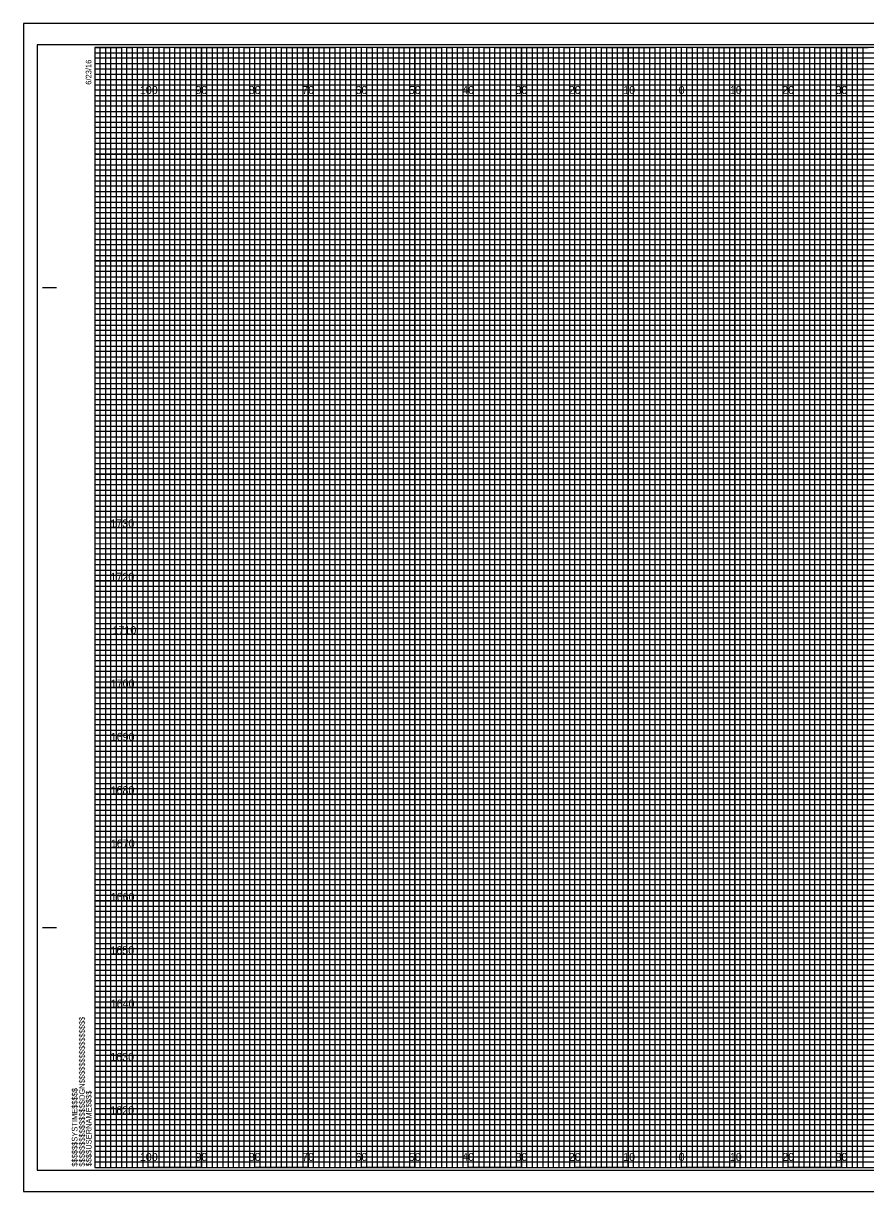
# Model space of a CAD drawing. Extents: x -13 to 323, y -5 to 6154.
# Drawn here: x -13.4 to 144.5, y 2415.5 to 2634.5 of the extents above; entities that cross this region are included whole.
import ezdxf

# ---------------------------------------------------------------- set-up
doc = ezdxf.new("R2010")
doc.units = 0
for name, color, linetype in [('Prop Retaining Wall', 7, 'Continuous'), ('Prop XS Alignment Label', 7, 'Continuous'), ('Prop XS DDE', 7, 'Continuous'), ('Prop XS DDE Elevations', 7, 'Continuous'), ('Prop XS DDE Slope Text', 7, 'Continuous'), ('Prop XS Earthwork Shape', 7, 'Continuous'), ('Prop XS Elevation Labels', 7, 'Continuous'), ('Prop XS Station Labels', 7, 'Continuous'), ('Raster_Level_0', 7, 'Continuous'), ('Scratch_Level_3', 7, 'Continuous'), ('Sheet Cutting Line CELL', 7, 'Continuous')]:
    doc.layers.add(name, color=color, linetype=linetype)

msp = doc.modelspace()

# ---------------------------------------------------------------- linework, layer by layer
at = {"layer": 'Prop Retaining Wall'}
for p, q in [((0, 2629), (260, 2629)), ((260, 2627.98), (0, 2627.98)), ((0, 2627.98), (0, 2627)), ((0, 2627), (260, 2627)), ((260, 2625.89), (0, 2625.89)), ((0, 2625.89), (0, 2624)), ((0, 2624), (320, 2624))]:
    msp.add_line(p, q, dxfattribs=at)
for points in [[(0, 2623), (270, 2623), (320, 2623), (320, 2622), (0, 2622)], [(0, 2621), (320, 2621), (320, 2619), (0, 2619)], [(0, 2618), (320, 2618), (320, 2617), (0, 2616.98)], [(0, 2616), (320, 2616), (320, 2614), (0, 2614)], [(0, 2613), (320, 2613), (320, 2612), (0, 2612)], [(0, 2611), (320, 2611), (320, 2609), (0, 2609)], [(0, 2608), (320, 2608), (320, 2607), (0, 2607)], [(0, 2606), (320, 2606), (320, 2604), (0, 2604)], [(0, 2603), (320, 2603), (320, 2602), (0, 2602)], [(0, 2601), (320, 2601), (320, 2599), (0, 2599)], [(0, 2598), (320, 2598), (320, 2597), (0, 2597)], [(0, 2596), (320, 2596), (320, 2593.95), (320, 2593), (320, 2592), (0, 2592)], [(0, 2594), (320, 2594), (320, 2593), (0, 2593)], [(0, 2591), (320, 2591), (320, 2589), (0, 2589.03)], [(0, 2589.03), (320, 2589), (320, 2588), (0, 2588)], [(0, 2587), (320, 2587), (320, 2586), (0, 2586)], [(0, 2584), (320, 2584), (320, 2583), (0, 2583)], [(0, 2582), (320, 2582), (320, 2581), (0, 2581)], [(-0.07, 2578.89), (320, 2578.89), (320, 2577.88), (-0.07, 2577.88)], [(0, 2577), (320, 2577), (320, 2576), (0, 2576)], [(0, 2574), (320, 2574), (320, 2573), (0, 2573)], [(0, 2572), (320, 2572), (320, 2571), (0, 2571)], [(0, 2569), (320, 2569), (320, 2568), (0, 2568)], [(0, 2567), (320, 2567), (320, 2566), (0, 2566)], [(0, 2564), (320, 2564), (320, 2563), (0, 2563)], [(0, 2562), (320, 2562), (320, 2561), (0, 2561)], [(0, 2559), (320, 2559), (319.99, 2557.98), (0, 2558)], [(0, 2557), (320, 2557), (320, 2556), (0, 2556)], [(0, 2554), (320, 2554), (320, 2553), (0, 2553)], [(0, 2552), (320, 2552), (320, 2551), (0, 2551)], [(0, 2549), (320, 2549), (320, 2548), (0, 2548)], [(0, 2547), (320, 2547), (320, 2546), (0, 2546)], [(0, 2544), (320, 2544), (320, 2543), (0, 2543)], [(0, 2542), (320, 2542), (320, 2541), (0, 2541)], [(0, 2539), (320, 2539), (320, 2538), (0, 2538)], [(0, 2536.99), (320.07, 2536.91), (320, 2536), (0, 2536)], [(0, 2534), (320, 2534), (320, 2533), (0, 2533)], [(0, 2532), (320, 2532), (320, 2531), (0, 2531)], [(0, 2529), (320, 2529), (320, 2528), (0, 2528)], [(0, 2527), (320, 2527), (320, 2526), (0, 2526)], [(0, 2524), (320, 2524), (320, 2523), (0, 2523)], [(0, 2522), (320, 2522), (320, 2521), (0, 2521)], [(0, 2519), (320, 2519), (320, 2518), (0, 2518)], [(0, 2517), (320, 2517), (320, 2516), (0, 2516)], [(0, 2514), (320, 2514), (320, 2513), (0, 2513)], [(0, 2512), (320, 2512), (320, 2511), (0, 2511)], [(0, 2509), (320, 2509), (320, 2508), (0, 2508)], [(0, 2507), (320, 2507), (320, 2506), (0, 2506)], [(0, 2504), (320, 2504), (320, 2503), (0, 2503)], [(0, 2502), (320, 2502), (320, 2501), (0, 2501)], [(0, 2499), (320, 2499), (319.99, 2497.98), (0, 2498)], [(0, 2497), (320, 2497), (320, 2496), (0, 2496)], [(0, 2494), (320, 2494), (320, 2493), (0, 2493)], [(0, 2492), (320, 2492), (320, 2491), (0, 2491)], [(0, 2489), (320, 2489), (320, 2488), (0, 2488)], [(0, 2487), (320, 2487), (320, 2486), (0, 2486)], [(0, 2484), (320, 2484), (320, 2483), (0, 2483)], [(0, 2482), (320, 2482), (320, 2481), (0, 2481)], [(0, 2479), (320, 2479), (320, 2478), (0, 2478)], [(0, 2476.99), (320.07, 2476.91), (320, 2476), (0, 2476)], [(0, 2474), (320, 2474), (320, 2473), (0, 2473)], [(0, 2472), (320, 2472), (320, 2471), (0, 2471)], [(0, 2469), (320, 2469), (320, 2468), (0, 2468)], [(0, 2467), (320, 2467), (320, 2466), (0, 2466)], [(0, 2464), (320, 2464), (320, 2463), (0, 2463)], [(0, 2462), (320, 2462), (320, 2461), (0, 2461)], [(0, 2459), (320, 2459), (320, 2458), (0, 2458)], [(0, 2457), (320, 2457), (320, 2456), (0, 2456)], [(0, 2454), (320, 2454), (320, 2453), (0, 2453)], [(0, 2452), (320, 2452), (320, 2451), (0, 2451)], [(0, 2449), (320, 2449), (320, 2448), (0, 2448)], [(0, 2447), (320, 2447), (320, 2446), (0, 2446)], [(0, 2444), (320, 2444), (320, 2443), (0, 2443)], [(0, 2442), (320, 2442), (320, 2441), (0, 2441)], [(0, 2439), (320, 2439), (320, 2438), (0, 2438)], [(0, 2437), (320, 2437), (320, 2436), (0, 2436)], [(0, 2434), (320, 2434), (320, 2433), (0, 2433)], [(0, 2432), (320, 2432), (320, 2431), (0, 2431)], [(0, 2429), (320, 2429), (320, 2428), (0, 2428)], [(0, 2427), (320, 2427), (320, 2426), (0, 2426)], [(0, 2424), (320, 2424), (320, 2423), (0, 2423)], [(0, 2422), (320, 2422), (320, 2421), (0, 2421)]]:
    msp.add_lwpolyline(points, dxfattribs=at)
at = {"layer": 'Prop XS Alignment Label'}
for p, q in [((-9.8, 2585), (-7.3, 2585)), ((-9.7, 2585), (-7.2, 2585)), ((-9.8, 2465), (-7.3, 2465)), ((-9.7, 2465), (-7.2, 2465)), ((0, 2420), (0, 2420)), ((0, 2420), (0, 2420)), ((0, 2420), (0, 2420)), ((0, 2420), (0, 2420)), ((0, 2420), (0, 2420)), ((0, 2420), (0, 2420)), ((0, 2420), (0, 2420))]:
    msp.add_line(p, q, dxfattribs=at)
msp.add_lwpolyline([(320, 2630), (0, 2630), (0, 2420), (320, 2420)], close=True, dxfattribs=at)
at = {"layer": 'Prop XS DDE'}
msp.add_lwpolyline([(-13.4, 2415.5), (323.3, 2415.5), (323.3, 2634.5), (-13.4, 2634.5)], close=True, dxfattribs=at)
at = {"layer": 'Prop XS DDE Elevations'}
for p, q in [((10, 2420), (10, 2630)), ((20, 2420), (20, 2630)), ((30, 2420), (30, 2630)), ((40, 2420), (40, 2630)), ((50, 2420), (50, 2630)), ((60, 2420), (60, 2630)), ((70, 2420), (70, 2630)), ((80, 2420), (80, 2630)), ((90, 2420), (90, 2630)), ((100, 2420), (100, 2630)), ((110, 2420), (110, 2630)), ((120, 2420), (120, 2630)), ((130, 2420), (130, 2630)), ((140, 2420), (140, 2630)), ((0, 2620), (320, 2620)), ((0, 2610), (320, 2610)), ((0, 2600), (320, 2600)), ((0, 2590), (320, 2590)), ((0, 2580), (320, 2580)), ((0, 2570), (320, 2570)), ((0, 2560), (320, 2560)), ((0, 2550), (320, 2550)), ((0, 2540), (320, 2540)), ((0, 2530), (320, 2530)), ((0, 2520), (320, 2520)), ((0, 2510), (320, 2510)), ((0, 2500), (320, 2500)), ((0, 2490), (320, 2490)), ((0, 2480), (320, 2480)), ((0, 2470), (320, 2470)), ((0, 2460), (320, 2460)), ((0, 2450), (320, 2450)), ((0, 2440), (320, 2440)), ((0, 2430), (320, 2430))]:
    msp.add_line(p, q, dxfattribs=at)
at = {"layer": 'Prop XS DDE Slope Text'}
msp.add_lwpolyline([(-10.8, 2419.5), (322.4, 2419.5), (322.4, 2630.5), (-10.8, 2630.5)], close=True, dxfattribs=at)
at = {"layer": 'Prop XS Earthwork Shape'}
for p, q in [((10, 2630), (0, 2630)), ((10, 2420), (10, 2630)), ((30, 2630), (20, 2630)), ((20, 2630), (20, 2420)), ((30, 2420), (30, 2630)), ((50, 2630), (40, 2630)), ((40, 2630), (40, 2420)), ((50, 2420), (50, 2630)), ((70, 2630), (60, 2630)), ((60, 2630), (60, 2420)), ((70, 2420), (70, 2630)), ((90, 2630), (80, 2630)), ((80, 2630), (80, 2420)), ((90, 2420), (90, 2630)), ((110, 2630), (100, 2630)), ((100, 2630), (100, 2420)), ((110, 2420), (110, 2630)), ((130, 2630), (120, 2630)), ((120, 2630), (120, 2420)), ((130, 2420), (130, 2630)), ((150, 2630), (140, 2630)), ((140, 2630), (140, 2420)), ((20, 2420), (10, 2420)), ((40, 2420), (30, 2420)), ((60, 2420), (50, 2420)), ((80, 2420), (70, 2420)), ((100, 2420), (90, 2420)), ((120, 2420), (110, 2420)), ((140, 2420), (130, 2420))]:
    msp.add_line(p, q, dxfattribs=at)
for points in [[(0, 2620), (320, 2620), (320, 2610), (0, 2610)], [(0, 2600), (320, 2600), (320, 2590), (0, 2590)], [(0, 2580), (320, 2580), (320, 2570), (0, 2570)], [(0, 2560), (320, 2560), (320, 2550), (0, 2550)], [(0, 2540), (320, 2540), (320, 2530), (0, 2530)], [(0, 2520), (320, 2520), (320, 2510), (0, 2510)], [(0, 2500), (320, 2500), (320, 2490), (0, 2490)], [(0, 2480), (320, 2480), (320, 2470), (0, 2470)], [(0, 2460), (320, 2460), (320, 2450), (0, 2450)], [(0, 2440), (320, 2440), (320, 2430), (0, 2430)]]:
    msp.add_lwpolyline(points, dxfattribs=at)
at = {"layer": 'Prop XS Elevation Labels'}
for points in [[(0, 2420), (1, 2420), (1, 2630), (2, 2630), (2, 2420)], [(2, 2420), (3, 2420), (3, 2630), (4, 2630), (4, 2420)], [(5, 2420), (6, 2420), (6, 2630), (7, 2630), (7, 2420)], [(7, 2420), (8, 2420), (8, 2630), (9, 2630), (9, 2420)], [(10, 2420), (11, 2420), (11, 2630), (12, 2630), (12, 2420)], [(12, 2420), (13, 2420), (13, 2630), (14, 2630), (14, 2420)], [(15, 2420), (16, 2420), (16, 2630), (17, 2630), (17, 2420)], [(17, 2420), (18, 2420), (18, 2630), (19, 2630), (19, 2420)], [(20, 2420), (21, 2420), (21, 2630), (22, 2630), (22, 2420)], [(22, 2420), (23, 2420), (23, 2630), (24, 2630), (24, 2420)], [(25, 2420), (26, 2420), (26, 2630), (27, 2630), (27, 2420)], [(27, 2420), (28, 2420), (28, 2630), (29, 2630), (29, 2420)], [(30, 2420), (31, 2420), (31, 2630), (32, 2630), (32, 2420)], [(32, 2420), (33, 2420), (33, 2630), (34, 2630), (34, 2420)], [(35, 2420), (36, 2420), (36, 2630), (37, 2630), (37, 2420)], [(37, 2420), (38, 2420), (38, 2630), (39, 2630), (39, 2420)], [(40, 2420), (41, 2420), (41, 2630), (42, 2630), (42, 2420)], [(42, 2420), (43, 2420), (43, 2630), (44, 2630), (44, 2420)], [(45, 2420), (46, 2420), (46, 2630), (47, 2630), (47, 2420)], [(47, 2420), (48, 2420), (48, 2630), (49, 2630), (49, 2420)], [(50, 2420), (51, 2420), (51, 2630), (52, 2630), (52, 2420)], [(52, 2420), (53, 2420), (53, 2630), (54, 2630), (54, 2420)], [(55, 2420), (56, 2420), (56, 2630), (57, 2630), (57, 2420)], [(57, 2420), (58, 2420), (58, 2630), (59, 2630), (59, 2420)], [(60, 2420), (61, 2420), (61, 2630), (62, 2630), (62, 2420)], [(62, 2420), (63, 2420), (63, 2630), (64, 2630), (64, 2420)], [(65, 2420), (66, 2420), (66, 2630), (67, 2630), (67, 2420)], [(67, 2420), (68, 2420), (68, 2630), (69, 2630), (69, 2420)], [(70, 2420), (71, 2420), (71, 2630), (72, 2630), (72, 2420)], [(72, 2420), (73, 2420), (73, 2630), (74, 2630), (74, 2420)], [(75, 2420), (76, 2420), (76, 2630), (77, 2630), (77, 2420)], [(77, 2420), (78, 2420), (78, 2630), (79, 2630), (79, 2420)], [(80, 2420), (81, 2420), (81, 2630), (82, 2630), (82, 2420)], [(82, 2420), (83, 2420), (83, 2630), (84, 2630), (84, 2420)], [(85, 2420), (86, 2420), (86, 2630), (87, 2630), (87, 2420)], [(87, 2420), (88, 2420), (88, 2630), (89, 2630), (89, 2420)], [(90, 2420), (91, 2420), (91, 2630), (92, 2630), (92, 2420)], [(92, 2420), (93, 2420), (93, 2630), (94, 2630), (94, 2420)], [(95, 2420), (96, 2420), (96, 2630), (97, 2630), (97, 2420)], [(97, 2420), (98, 2420), (98, 2630), (99, 2630), (99, 2420)], [(100, 2420), (101, 2420), (101, 2630), (102, 2630), (102, 2420)], [(102, 2420), (103, 2420), (103, 2630), (104, 2630), (104, 2420)], [(105, 2420), (106, 2420), (106, 2630), (107, 2630), (107, 2420)], [(107, 2420), (108, 2420), (108, 2630), (109, 2630), (109, 2420)], [(110, 2420), (111, 2420), (111, 2630), (112, 2630), (112, 2420)], [(112, 2420), (113, 2420), (113, 2630), (114, 2630), (114, 2420)], [(115, 2420), (116, 2420), (116, 2630), (117, 2630), (117, 2420)], [(117, 2420), (118, 2420), (118, 2630), (119, 2630), (119, 2420)], [(120, 2420), (121, 2420), (121, 2630), (122, 2630), (122, 2420)], [(122, 2420), (123, 2420), (123, 2630), (124, 2630), (124, 2420)], [(125, 2420), (126, 2420), (126, 2630), (127, 2630), (127, 2420)], [(127, 2420), (128, 2420), (128, 2630), (129, 2630), (129, 2420)], [(130, 2420), (131, 2420), (131, 2630), (132, 2630), (132, 2420)], [(132, 2420), (133, 2420), (133, 2630), (134, 2630), (134, 2420)], [(135, 2420), (136, 2420), (136, 2630), (137, 2630), (137, 2420)], [(137, 2420), (138, 2420), (138, 2630), (139, 2630), (139, 2420)], [(140, 2420), (141, 2420), (141, 2630), (142, 2630), (142, 2420)], [(142, 2420), (143, 2420), (143, 2630), (144, 2630), (144, 2420)]]:
    msp.add_lwpolyline(points, dxfattribs=at)
at = {"layer": 'Prop XS Station Labels'}
for points in [[(0, 2630), (5, 2630), (5, 2420), (15, 2420), (15, 2630), (25, 2630), (25, 2420), (35, 2420), (35, 2630), (45, 2630), (45, 2420), (55, 2420), (55, 2630), (65, 2630), (65, 2420), (75, 2420), (75, 2630), (85, 2630), (85, 2420), (95, 2420), (95, 2630), (105, 2630), (105, 2420), (115, 2420), (115, 2630), (125, 2630), (125, 2420), (135, 2420), (135, 2630), (145, 2630)], [(0, 2625), (275, 2625)], [(0, 2605), (320, 2605), (320, 2615), (0, 2615)], [(0, 2585), (320, 2585), (320, 2595), (0, 2595)], [(0, 2565), (320, 2565), (320, 2575), (0, 2575)], [(0, 2545), (320, 2545), (320, 2555), (0, 2555)], [(0, 2525), (320, 2525), (320, 2535), (0, 2535)], [(0, 2505), (320, 2505), (320, 2515), (0, 2515)], [(0, 2485), (320, 2485), (320, 2495), (0, 2495)], [(0, 2465), (320, 2465), (320, 2475), (0, 2475)], [(0, 2445), (320, 2445), (320, 2455), (0, 2455)], [(0, 2425), (320, 2425), (320, 2435), (0, 2435)]]:
    msp.add_lwpolyline(points, dxfattribs=at)
at = {"layer": 'Sheet Cutting Line CELL'}
for p, q in [((323.3, 2634.5), (-13.4, 2634.5)), ((-13.4, 2634.5), (-13.4, 2415.5)), ((-13.4, 2415.5), (323.3, 2415.5))]:
    msp.add_line(p, q, dxfattribs=at)

# ---------------------------------------------------------------- texts
at = {"layer": 'Prop XS Alignment Label'}
for s, p in [('6/23/16', (-0.65, 2623)), ('$$$$$$$$$$$$$$$$DGN$$$$$$$$$$$$$$$$', (-1.88, 2420.18)), ('$$$$$$SYSTIME$$$$$', (-3.26, 2420.18)), ('$$$$USERNAME$$$$', (-0.62, 2420.23))]:
    msp.add_text(s, height=1.05, rotation=90, dxfattribs=at).set_placement(p)
at = {"layer": 'Raster_Level_0'}
for s, p in [('100', (8.44, 2621.25)), ('90', (18.86, 2621.25)), ('80', (28.86, 2621.25)), ('70', (38.86, 2621.25)), ('60', (48.86, 2621.25)), ('50', (58.86, 2621.25)), ('40', (68.86, 2621.25)), ('30', (78.86, 2621.25)), ('20', (88.86, 2621.25)), ('10', (99.04, 2621.25)), ('0', (109.45, 2621.25)), ('0', (109.45, 2621.25)), ('10', (119.04, 2621.25)), ('20', (128.86, 2621.25)), ('30', (138.86, 2621.25)), ('100', (8.44, 2421.25)), ('90', (18.86, 2421.25)), ('80', (28.86, 2421.25)), ('70', (38.86, 2421.25)), ('60', (48.86, 2421.25)), ('50', (58.86, 2421.25)), ('40', (68.86, 2421.25)), ('30', (78.86, 2421.25)), ('20', (88.86, 2421.25)), ('10', (99.04, 2421.25)), ('0', (109.45, 2421.25)), ('0', (109.45, 2421.25)), ('10', (119.04, 2421.25)), ('20', (128.86, 2421.25)), ('30', (138.86, 2421.25))]:
    msp.add_text(s, height=1.5, dxfattribs=at).set_placement(p)
at = {"layer": 'Scratch_Level_3'}
for s, p in [('1730', (2.92, 2540)), ('1720', (2.93, 2530)), ('1710', (3.31, 2520)), ('1700', (2.98, 2510)), ('1690', (2.97, 2500)), ('1680', (2.95, 2490)), ('1670', (3, 2480)), ('1660', (2.97, 2470)), ('1650', (2.92, 2460)), ('1640', (2.97, 2450)), ('1630', (2.89, 2440)), ('1620', (2.9, 2430))]:
    msp.add_text(s, height=1.5, dxfattribs=at).set_placement(p)

doc.saveas('drawing.dxf')
